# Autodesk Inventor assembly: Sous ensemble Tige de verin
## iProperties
Created: 2004-11
Part Number: Sous ensemble Tige de verin
Document SubType Name: Assembly
Designer: Bruno
Manufacturer: Standard
Standards Organization: Custom
Norme de conversion: STEP AP203
Nom du fichier: Take Out.stp
Préprocesseur: Mechanical Desktop 2005
Postprocesseur: Build: 096e, Release: 9 RTM - Date: Thu 06/17/2004
Unités envoyées: MILLIMETERS
Incertitude: 1.0000000000000002e-06
Author: Bruno
